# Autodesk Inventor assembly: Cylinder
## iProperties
Created: 2007-04
Part Number: Cylinder
Document SubType Name: Assembly
Designer: kurs1
Manufacturer: Standard
Standards Organization: Custom
Author: kurs1
